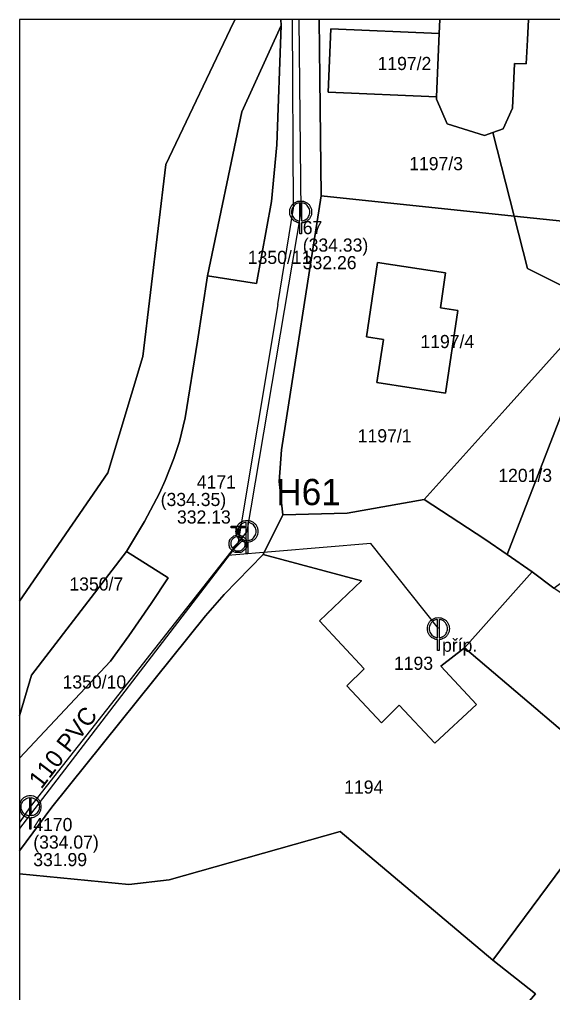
# Model space of a CAD drawing. Extents: x -559956 to -559707, y -1077221 to -1076919.
# Drawn here: x -559956.3 to -559895.5, y -1077029.9 to -1076918.8 of the extents above; entities that cross this region are included whole.
import ezdxf

# ---------------------------------------------------------------- set-up
doc = ezdxf.new("R2010")
doc.units = 0
for name, color, linetype in [('Hydrant', 7, 'Continuous'), ('Kanalizační přípojka', 7, 'Continuous'), ('Kanalizační stoka', 7, 'Continuous'), ('Kanalizační šachta', 7, 'Continuous'), ('Označení hydrantu', 7, 'Continuous'), ('Parcela-polygon', 7, 'Continuous'), ('Parcela-text', 7, 'Continuous'), ('Popis šachty', 7, 'Continuous'), ('Vodovodní řad', 7, 'Continuous'), ('Řad vodovodní popis', 7, 'Continuous')]:
    doc.layers.add(name, color=color, linetype=linetype)

msp = doc.modelspace()

# ---------------------------------------------------------------- linework, layer by layer
at = {"layer": 'Hydrant'}
for points in [[(-559931.43, -1076977.63), (-559931.43, -1076976.82), (-559932.12, -1076976.82), (-559932.12, -1076976.63), (-559930.55, -1076976.63), (-559930.55, -1076976.82), (-559931.24, -1076976.82), (-559931.24, -1076977.63)], [(-559931.98, -1076979.14), (-559930.83, -1076977.99)], [(-559930.7, -1076978.13), (-559931.84, -1076979.27)]]:
    msp.add_lwpolyline(points, dxfattribs=at)
for points in [[(-559931.24, -1076977.63), (-559930.88, -1076977.66), (-559930.63, -1076977.92), (-559930.34, -1076978.22), (-559930.34, -1076978.63), (-559930.34, -1076979.05), (-559930.63, -1076979.34), (-559930.92, -1076979.63), (-559931.34, -1076979.63), (-559931.75, -1076979.63), (-559932.04, -1076979.34), (-559932.34, -1076979.05), (-559932.34, -1076978.63), (-559932.34, -1076978.22), (-559932.04, -1076977.92), (-559931.79, -1076977.66), (-559931.43, -1076977.63)], [(-559930.83, -1076977.99), (-559931.05, -1076977.82), (-559931.34, -1076977.82), (-559931.68, -1076977.82), (-559931.91, -1076978.05), (-559932.15, -1076978.29), (-559932.15, -1076978.63), (-559932.15, -1076978.92), (-559931.98, -1076979.14)], [(-559931.84, -1076979.27), (-559931.63, -1076979.44), (-559931.34, -1076979.44), (-559931, -1076979.44), (-559930.76, -1076979.2), (-559930.53, -1076978.97), (-559930.53, -1076978.63), (-559930.53, -1076978.34), (-559930.7, -1076978.13)]]:
    msp.add_open_spline(points, degree=3, dxfattribs=at)
at = {"layer": 'Kanalizační přípojka'}
msp.add_lwpolyline([(-559908.48, -1076988.31), (-559916.18, -1076978.61), (-559932.48, -1076979.97)], dxfattribs=at)
at = {"layer": 'Kanalizační stoka'}
for p, q in [((-559924.39, -1076918.77), (-559924.19, -1076940.75)), ((-559924.19, -1076940.75), (-559930.32, -1076977.22)), ((-559930.32, -1076977.22), (-559955.04, -1077008.65)), ((-559955.04, -1077008.65), (-559956.27, -1077010.45))]:
    msp.add_line(p, q, dxfattribs=at)
at = {"layer": 'Kanalizační šachta'}
for p, q in [((-559956.27, -1077008.41), (-559956.27, -1077008.88)), ((-559955.14, -1077007.61), (-559955.14, -1077009.68)), ((-559954.94, -1077009.68), (-559954.94, -1077007.61))]:
    msp.add_line(p, q, dxfattribs=at)
for points in [[(-559924.29, -1076941.78), (-559924.29, -1076939.71)], [(-559924.09, -1076939.71), (-559924.09, -1076941.78)], [(-559924.09, -1076941.99), (-559924.09, -1076943.25), (-559924.29, -1076943.25), (-559924.29, -1076941.99)], [(-559930.42, -1076978.25), (-559930.42, -1076976.18)], [(-559930.22, -1076976.18), (-559930.22, -1076978.25)], [(-559930.22, -1076978.46), (-559930.22, -1076979.72), (-559930.42, -1076979.72), (-559930.42, -1076978.46)], [(-559908.59, -1076989.35), (-559908.59, -1076987.27)], [(-559908.38, -1076987.27), (-559908.38, -1076989.35)], [(-559908.38, -1076989.56), (-559908.38, -1076990.81), (-559908.59, -1076990.81), (-559908.59, -1076989.56)], [(-559955.14, -1077009.89), (-559955.14, -1077011.15), (-559954.94, -1077011.15), (-559954.94, -1077009.89)]]:
    msp.add_lwpolyline(points, dxfattribs=at)
for points in [[(-559924.29, -1076941.99), (-559924.55, -1076941.98), (-559924.81, -1076941.83), (-559925.11, -1076941.67), (-559925.27, -1076941.37), (-559925.44, -1076941.07), (-559925.44, -1076940.75), (-559925.44, -1076940.42), (-559925.27, -1076940.12), (-559925.1, -1076939.82), (-559924.8, -1076939.66), (-559924.51, -1076939.5), (-559924.19, -1076939.5), (-559923.87, -1076939.5), (-559923.57, -1076939.66), (-559923.27, -1076939.82), (-559923.11, -1076940.12), (-559922.94, -1076940.42), (-559922.94, -1076940.75), (-559922.94, -1076941.07), (-559923.1, -1076941.37), (-559923.27, -1076941.67), (-559923.57, -1076941.83), (-559923.83, -1076941.98), (-559924.09, -1076941.99)], [(-559924.29, -1076939.71), (-559924.49, -1076939.73), (-559924.7, -1076939.84), (-559924.95, -1076939.98), (-559925.09, -1076940.23), (-559925.23, -1076940.48), (-559925.23, -1076940.75), (-559925.23, -1076941.02), (-559925.09, -1076941.26), (-559924.96, -1076941.51), (-559924.71, -1076941.65), (-559924.5, -1076941.77), (-559924.29, -1076941.78)], [(-559924.09, -1076941.78), (-559923.88, -1076941.77), (-559923.67, -1076941.65), (-559923.42, -1076941.51), (-559923.28, -1076941.26), (-559923.15, -1076941.02), (-559923.15, -1076940.75), (-559923.15, -1076940.48), (-559923.29, -1076940.23), (-559923.43, -1076939.98), (-559923.68, -1076939.84), (-559923.89, -1076939.73), (-559924.09, -1076939.71)], [(-559930.42, -1076978.46), (-559930.68, -1076978.45), (-559930.94, -1076978.3), (-559931.24, -1076978.14), (-559931.4, -1076977.84), (-559931.57, -1076977.54), (-559931.57, -1076977.22), (-559931.57, -1076976.89), (-559931.4, -1076976.59), (-559931.23, -1076976.29), (-559930.93, -1076976.13), (-559930.64, -1076975.97), (-559930.32, -1076975.97), (-559930, -1076975.97), (-559929.7, -1076976.13), (-559929.4, -1076976.29), (-559929.24, -1076976.59), (-559929.07, -1076976.89), (-559929.07, -1076977.22), (-559929.07, -1076977.54), (-559929.23, -1076977.84), (-559929.4, -1076978.14), (-559929.7, -1076978.3), (-559929.96, -1076978.45), (-559930.22, -1076978.46)], [(-559930.42, -1076976.18), (-559930.62, -1076976.2), (-559930.83, -1076976.31), (-559931.08, -1076976.45), (-559931.22, -1076976.7), (-559931.36, -1076976.95), (-559931.36, -1076977.22), (-559931.36, -1076977.49), (-559931.22, -1076977.73), (-559931.09, -1076977.98), (-559930.84, -1076978.12), (-559930.63, -1076978.24), (-559930.42, -1076978.25)], [(-559930.22, -1076978.25), (-559930.01, -1076978.24), (-559929.8, -1076978.12), (-559929.55, -1076977.98), (-559929.41, -1076977.73), (-559929.28, -1076977.49), (-559929.28, -1076977.22), (-559929.28, -1076976.95), (-559929.42, -1076976.7), (-559929.56, -1076976.45), (-559929.81, -1076976.31), (-559930.02, -1076976.2), (-559930.22, -1076976.18)], [(-559908.59, -1076989.56), (-559908.84, -1076989.54), (-559909.11, -1076989.4), (-559909.4, -1076989.23), (-559909.57, -1076988.93), (-559909.73, -1076988.64), (-559909.73, -1076988.31), (-559909.73, -1076987.98), (-559909.56, -1076987.68), (-559909.4, -1076987.38), (-559909.1, -1076987.22), (-559908.8, -1076987.06), (-559908.48, -1076987.06), (-559908.17, -1076987.06), (-559907.87, -1076987.22), (-559907.57, -1076987.38), (-559907.4, -1076987.68), (-559907.23, -1076987.98), (-559907.23, -1076988.31), (-559907.23, -1076988.64), (-559907.4, -1076988.93), (-559907.56, -1076989.23), (-559907.86, -1076989.4), (-559908.12, -1076989.54), (-559908.38, -1076989.56)], [(-559908.59, -1076987.27), (-559908.78, -1076987.29), (-559909, -1076987.41), (-559909.25, -1076987.54), (-559909.39, -1076987.79), (-559909.53, -1076988.04), (-559909.53, -1076988.31), (-559909.53, -1076988.58), (-559909.39, -1076988.83), (-559909.25, -1076989.08), (-559909, -1076989.21), (-559908.79, -1076989.33), (-559908.59, -1076989.35)], [(-559908.38, -1076989.35), (-559908.18, -1076989.33), (-559907.96, -1076989.21), (-559907.71, -1076989.08), (-559907.58, -1076988.83), (-559907.44, -1076988.58), (-559907.44, -1076988.31), (-559907.44, -1076988.04), (-559907.58, -1076987.79), (-559907.72, -1076987.54), (-559907.97, -1076987.41), (-559908.18, -1076987.29), (-559908.38, -1076987.27)], [(-559954.94, -1077009.89), (-559954.68, -1077009.88), (-559954.42, -1077009.73), (-559954.12, -1077009.57), (-559953.95, -1077009.27), (-559953.79, -1077008.97), (-559953.79, -1077008.65), (-559953.79, -1077008.32), (-559953.96, -1077008.02), (-559954.12, -1077007.72), (-559954.42, -1077007.56), (-559954.72, -1077007.4), (-559955.04, -1077007.4), (-559955.36, -1077007.4), (-559955.65, -1077007.56), (-559955.95, -1077007.72), (-559956.12, -1077008.02), (-559956.23, -1077008.21), (-559956.27, -1077008.41)], [(-559955.14, -1077009.68), (-559955.35, -1077009.67), (-559955.56, -1077009.55), (-559955.81, -1077009.41), (-559955.94, -1077009.16), (-559956.08, -1077008.92), (-559956.08, -1077008.65), (-559956.08, -1077008.38), (-559955.94, -1077008.13), (-559955.8, -1077007.88), (-559955.55, -1077007.74), (-559955.34, -1077007.63), (-559955.14, -1077007.61)], [(-559954.94, -1077007.61), (-559954.74, -1077007.63), (-559954.53, -1077007.74), (-559954.28, -1077007.88), (-559954.14, -1077008.13), (-559954, -1077008.38), (-559954, -1077008.65), (-559954, -1077008.92), (-559954.13, -1077009.16), (-559954.27, -1077009.41), (-559954.52, -1077009.55), (-559954.73, -1077009.67), (-559954.94, -1077009.68)], [(-559956.27, -1077008.88), (-559956.23, -1077009.08), (-559956.12, -1077009.27), (-559955.96, -1077009.57), (-559955.66, -1077009.73), (-559955.4, -1077009.88), (-559955.14, -1077009.89)]]:
    msp.add_open_spline(points, degree=3, dxfattribs=at)
at = {"layer": 'Parcela-polygon'}
for p, q in [((-559931.65, -1076918.77), (-559956.27, -1076918.77)), ((-559956.27, -1076918.77), (-559956.27, -1076985.18)), ((-559926.47, -1076918.77), (-559931.65, -1076918.77)), ((-559922.08, -1076918.77), (-559926.47, -1076918.77)), ((-559908.31, -1076918.77), (-559922.08, -1076918.77)), ((-559898.19, -1076918.77), (-559908.31, -1076918.77)), ((-559876.97, -1076918.77), (-559898.19, -1076918.77)), ((-559956.27, -1076985.18), (-559956.27, -1076998.25)), ((-559956.27, -1076998.25), (-559956.27, -1077003.11)), ((-559956.27, -1077003.11), (-559956.27, -1077013.67)), ((-559956.27, -1077013.67), (-559956.27, -1077016.3)), ((-559956.27, -1077016.3), (-559956.27, -1077038.1))]:
    msp.add_line(p, q, dxfattribs=at)
for points in [[(-559926.47, -1076918.77), (-559926.41, -1076919.45), (-559926.92, -1076933.08), (-559927.5, -1076939.57), (-559929.24, -1076948.93), (-559934.81, -1076948.05), (-559935.97, -1076955.51), (-559937.36, -1076964.24), (-559938, -1076966.97), (-559938.64, -1076968.88), (-559939.64, -1076971.4), (-559940.28, -1076972.84), (-559942.02, -1076976.09), (-559944.06, -1076979.5), (-559939.32, -1076982.52), (-559941.23, -1076985.44), (-559943.79, -1076989.12), (-559945.87, -1076992.02), (-559956.27, -1077003.11)], [(-559956.27, -1077013.67), (-559952.59, -1077008.71), (-559935.04, -1076986.85), (-559932.9, -1076984.41), (-559928.46, -1076979.86), (-559926.22, -1076975.34), (-559926.64, -1076971.53), (-559926.36, -1076967.89), (-559921.87, -1076938.92), (-559922.02, -1076925.49), (-559922.08, -1076918.77)], [(-559956.27, -1076985.18), (-559946.18, -1076970.53), (-559942.18, -1076957.26), (-559939.56, -1076935.32), (-559931.86, -1076919.12), (-559931.65, -1076918.77)], [(-559931.65, -1076918.77), (-559931.86, -1076919.12), (-559939.56, -1076935.32), (-559942.18, -1076957.26), (-559946.18, -1076970.53), (-559956.27, -1076985.18)], [(-559956.27, -1076998.25), (-559954.89, -1076993.61), (-559944.06, -1076979.5), (-559942.02, -1076976.09), (-559940.28, -1076972.84), (-559939.64, -1076971.4), (-559938.64, -1076968.88), (-559938, -1076966.97), (-559937.36, -1076964.24), (-559935.97, -1076955.51), (-559934.81, -1076948.05), (-559930.89, -1076929.32), (-559926.41, -1076919.45), (-559926.47, -1076918.77)], [(-559922.08, -1076918.77), (-559922.02, -1076925.49), (-559921.87, -1076938.92), (-559899.85, -1076941.23), (-559902.28, -1076931.69), (-559903.21, -1076932.03), (-559907.48, -1076930.7), (-559908.7, -1076927.89), (-559908.69, -1076927.62), (-559921.07, -1076927.09), (-559920.74, -1076919.86), (-559908.38, -1076920.39), (-559908.31, -1076918.77)], [(-559908.31, -1076918.77), (-559908.38, -1076920.39), (-559908.69, -1076927.62), (-559908.7, -1076927.89), (-559907.48, -1076930.7), (-559903.21, -1076932.03), (-559902.28, -1076931.69), (-559901.08, -1076931.24), (-559900.02, -1076928.91), (-559899.79, -1076923.81), (-559898.47, -1076923.82), (-559898.32, -1076921.1), (-559898.19, -1076918.77)], [(-559898.19, -1076918.77), (-559898.32, -1076921.1), (-559898.47, -1076923.82), (-559899.79, -1076923.81), (-559900.02, -1076928.91), (-559901.08, -1076931.24), (-559902.28, -1076931.69), (-559899.85, -1076941.23), (-559886.22, -1076942.65), (-559876.97, -1076918.77)], [(-559876.97, -1076918.77), (-559886.22, -1076942.65), (-559900.64, -1076979.86), (-559897.77, -1076981.82), (-559895.32, -1076983.7), (-559890.33, -1076980.02), (-559878.13, -1076971.03), (-559872.38, -1076958.66), (-559870.8, -1076955.49), (-559867.94, -1076949.78), (-559878.66, -1076944.59), (-559871.24, -1076929.28), (-559861.21, -1076934.12), (-559856.1, -1076923.13), (-559871.69, -1076918.77)], [(-559956.27, -1077003.11), (-559945.87, -1076992.02), (-559943.79, -1076989.12), (-559941.23, -1076985.44), (-559939.32, -1076982.52), (-559944.06, -1076979.5), (-559954.89, -1076993.61), (-559956.27, -1076998.25)], [(-559956.27, -1077016.3), (-559943.78, -1077017.51), (-559939.19, -1077016.99), (-559919.7, -1077011.48), (-559902.26, -1077026.17), (-559888.94, -1077008.18), (-559887.45, -1077005.89), (-559905.49, -1076990.5), (-559908.19, -1076992.6), (-559904.13, -1076996.96), (-559908.89, -1077001.4), (-559912.96, -1076997.07), (-559914.97, -1076999.06), (-559918.91, -1076994.86), (-559916.93, -1076992.9), (-559922.03, -1076987.42), (-559917.26, -1076982.87), (-559928.46, -1076979.86), (-559932.9, -1076984.41), (-559935.04, -1076986.85), (-559952.59, -1077008.71), (-559956.27, -1077013.67)], [(-559956.27, -1077038.1), (-559931.69, -1077049.38), (-559937.39, -1077060.79), (-559940.03, -1077067.75), (-559934.19, -1077072.71), (-559917.05, -1077052.87), (-559899.67, -1077032.65), (-559897.39, -1077030), (-559902.26, -1077026.17), (-559919.7, -1077011.48), (-559939.19, -1077016.99), (-559943.78, -1077017.51), (-559956.27, -1077016.3)]]:
    msp.add_lwpolyline(points, dxfattribs=at)
for points in [[(-559926.41, -1076919.45), (-559930.89, -1076929.32), (-559934.81, -1076948.05), (-559929.24, -1076948.93), (-559927.5, -1076939.57), (-559926.92, -1076933.08)], [(-559921.07, -1076927.09), (-559908.69, -1076927.62), (-559908.38, -1076920.39), (-559920.74, -1076919.86)], [(-559890.11, -1076951.3), (-559898.32, -1076947.22), (-559899.85, -1076941.23), (-559921.87, -1076938.92), (-559926.36, -1076967.89), (-559926.64, -1076971.53), (-559926.22, -1076975.34), (-559918.88, -1076975.14), (-559910.09, -1076973.59), (-559900.85, -1076963.28)], [(-559899.85, -1076941.23), (-559898.32, -1076947.22), (-559890.11, -1076951.3), (-559900.85, -1076963.28), (-559910.09, -1076973.59), (-559903.2, -1076978.11), (-559900.64, -1076979.86), (-559886.22, -1076942.65)], [(-559915.51, -1076960.22), (-559907.68, -1076961.42), (-559906.26, -1076952.01), (-559908.24, -1076951.7), (-559907.66, -1076947.69), (-559915.41, -1076946.5), (-559916.68, -1076955), (-559914.76, -1076955.29)], [(-559907.68, -1076961.42), (-559915.51, -1076960.22), (-559914.76, -1076955.29), (-559916.68, -1076955), (-559915.41, -1076946.5), (-559907.66, -1076947.69), (-559908.24, -1076951.7), (-559906.26, -1076952.01)], [(-559926.22, -1076975.34), (-559928.46, -1076979.86), (-559917.26, -1076982.87), (-559922.03, -1076987.42), (-559916.93, -1076992.9), (-559918.91, -1076994.86), (-559914.97, -1076999.06), (-559912.96, -1076997.07), (-559908.89, -1077001.4), (-559904.13, -1076996.96), (-559908.19, -1076992.6), (-559905.49, -1076990.5), (-559897.77, -1076981.82), (-559900.64, -1076979.86), (-559903.2, -1076978.11), (-559910.09, -1076973.59), (-559918.88, -1076975.14)], [(-559895.32, -1076983.7), (-559897.77, -1076981.82), (-559905.49, -1076990.5), (-559887.45, -1077005.89), (-559885.99, -1077002.89), (-559884.16, -1076995.84), (-559882.97, -1076993.14), (-559882.57, -1076992.23)], [(-559888.94, -1077008.18), (-559902.26, -1077026.17), (-559897.39, -1077030), (-559899.67, -1077032.65), (-559890.87, -1077039.51), (-559889.51, -1077037.9), (-559886.76, -1077034.59), (-559883.82, -1077031.07), (-559882.16, -1077032.46), (-559880.99, -1077030.45), (-559880.21, -1077029.16), (-559888.42, -1077024.31), (-559880.14, -1077010.46)]]:
    msp.add_lwpolyline(points, close=True, dxfattribs=at)
at = {"layer": 'Vodovodní řad'}
msp.add_line((-559926.8, -1076951.31), (-559931.34, -1076978.63), dxfattribs=at)
for points in [[(-559926.8, -1076951.31), (-559924.99, -1076940.32), (-559925.12, -1076918.77)], [(-559931.34, -1076978.63), (-559956.27, -1077011.12)]]:
    msp.add_lwpolyline(points, dxfattribs=at)

# ---------------------------------------------------------------- texts
at = {"layer": 'Označení hydrantu'}
msp.add_text('H61', height=3, dxfattribs=at).set_placement((-559926.97, -1076974.22))
at = {"layer": 'Parcela-text'}
for s, p in [('1197/2', (-559915.42, -1076924.55)), ('1197/3', (-559911.81, -1076935.98)), ('1350/11', (-559930.22, -1076946.68)), ('1197/4', (-559910.53, -1076956.29)), ('1197/1', (-559917.68, -1076967.05)), ('1201/3', (-559901.65, -1076971.57)), ('1350/7', (-559950.57, -1076983.97)), ('1193', (-559913.55, -1076993.02)), ('1350/10', (-559951.35, -1076995.15)), ('1194', (-559919.23, -1077007.15))]:
    msp.add_text(s, height=1.5, dxfattribs=at).set_placement(p)
at = {"layer": 'Popis šachty'}
for s, p in [('67', (-559923.95, -1076943.28)), ('(334.33)', (-559923.95, -1076945.28)), ('332.26', (-559923.95, -1076947.28)), ('4171', (-559936.04, -1076972.32)), ('(334.35)', (-559940.16, -1076974.32)), ('332.13', (-559938.3, -1076976.32)), ('příp.', (-559908.06, -1076990.96)), ('4170', (-559954.69, -1077011.43)), ('(334.07)', (-559954.69, -1077013.43)), ('331.99', (-559954.69, -1077015.43))]:
    msp.add_text(s, height=1.5, dxfattribs=at).set_placement(p)
at = {"layer": 'Řad vodovodní popis'}
msp.add_text(' 110 PVC', height=2, rotation=52.498, dxfattribs=at).set_placement((-559954.23, -1077007.3))

doc.saveas('drawing.dxf')
